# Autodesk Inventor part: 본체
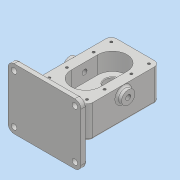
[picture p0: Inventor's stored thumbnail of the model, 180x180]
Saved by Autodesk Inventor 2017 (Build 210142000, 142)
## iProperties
Part Number: 본체
Material: 일반
Document SubType Name: Modeling
Designer: MRC
Density: 1 g/cm^3
Appearance: 기본값
Mass: 546.121 g
Surface Area: 823.386 cm^2
Volume: 546.121 cm^3
Author: MRC
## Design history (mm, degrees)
sketch "스케치1"
  geometry: L1 (40, -60)-(-40, -60); L2 (-40, -60)-(-40, 60); L3 (-40, 60)-(40, 60); L4 (40, 60)-(40, -60); L5 (40, -60)-(-40, 60); L6 (-40, -60)-(40, 60); 1 further point
  constraints: 12 end point, 2 midpoint, 2 parallel, 1 horizontal, 1 perpendicular
  dimensions: "d0" = 80 distance of L2.end L3.end; "d1" = 120 distance of L3.end L1.start
extrude "돌출1" new body sketch "스케치1" distance "d2" = 14; taper "d3" = 0 deg; dims "d5" = 39, "d6" = 0
fillet "모깎기1" dims "d4" = 9
sketch "스케치2"
  geometry: L1 (0, -49.175)-(0, 49.175); L2 (0, 22)-(0, -22); L3 (24, 22)-(24, -22); L4 (-24, -22)-(-24, 22); A1 r 24 centre (0, 22) between (24, 22) and (-24, 22); A2 r 24 centre (0, -22) between (-24, -22) and (24, -22); 2 further points
  constraints: 12 end point, 4 point on circle, 4 tangent, 2 centre point, 2 midpoint, 2 point on line, 1 coincident, 1 parallel, 1 vertical
  dimensions: "d12" = 22 distance of L2.start point (0, 0); "d13" = 24 radius of A1
extrude "돌출2" cut sketch "스케치2" distance "d14" = 29; taper "d15" = 0 deg
sketch "스케치3"
  geometry: C1 r 12.5 at (0, 22); C2 r 12.5 at (0, -22); A1 r 24 centre (0, 22) between (24, 22) and (-24, 22) reference; A2 r 24 centre (0, -22) between (-24, -22) and (24, -22) reference; 1 further point
  constraints: 2 centre point, 2 coincident
  dimensions: "d16" = 25 diameter of C1; "d17" = 25 diameter of C2
extrude "돌출3" cut sketch "스케치3" distance "d18" = 15; taper "d19" = 0 deg
chamfer "모따기1" distance "d20" = 1; stored, may be unused: second distance "d21" = 2, angle "d22" = 45 deg
sketch "스케치4"
  geometry: C1 r 19 at (0, 22); 1 further point
  constraints: 1 centre point, 1 vertical alignment
  dimensions: "d23" = 38 diameter of C1; "d24" = 22 distance of point (0, 0) C1.centre
extrude "돌출4" join sketch "스케치4" distance "d25" = 17; taper "d26" = 0 deg
sketch "스케치5"
  geometry: C1 r 19 at (0, 0) reference; C2 r 14 at (0, 0); 1 further point
  constraints: 1 centre point, 1 coincident
  dimensions: "d27" = 28 diameter of C2
extrude "돌출5" cut sketch "스케치5" distance "d28" = 7.3; taper "d29" = 0 deg
sketch "스케치6"
  geometry: C1 r 14 at (0, 0) reference; C2 r 8.5 at (0, 0); 1 further point
  constraints: 1 centre point, 1 coincident
  dimensions: "d30" = 17 diameter of C2
extrude "돌출6" cut sketch "스케치6" stored distance "d31" = 7.3; taper "d32" = 0 deg
fillet "모깎기2" dims "d33" = 0.5
sketch "스케치7"
  geometry: L1 (-80, 44)-(-90, 44); L2 (-90, 44)-(-90, -56); L3 (-90, -56)-(-80, -56); L4 (-80, -56)-(-80, 44); L5 (35.5, -15)-(46, -15) reference; L6 (46, -15)-(46, 14) reference; L7 (46, 14)-(60, 14) reference; L8 (60, 14)-(60, -39) reference; L9 (60, -39)-(41, -39) reference; L10 (41, -39)-(41, -56) reference; L11 (41, -56)-(36, -56) reference; L12 (36, -56)-(36, -49.2) reference; L13 (35.5, -48.7)-(30.5, -48.7) reference; L14 (30.5, -48.7)-(30.5, -30) reference; L15 (30.5, -30)-(34.5, -30) reference; L16 (34.5, -30)-(34.5, -16) reference; L17 (34.5, -16)-(35.5, -15) reference; L18 (-60, -39)-(-60, 14) reference; L19 (-60, 14)-(-46, 14) reference; L20 (-46, 14)-(-46, -15) reference; L21 (-46, -15)-(-35.5, -15) reference; L22 (-35.5, -15)-(-34.5, -16) reference; L23 (-34.5, -16)-(-34.5, -30) reference; L24 (-34.5, -30)-(-9.5, -30) reference; L25 (-9.5, -30)-(-9.5, -16) reference; L26 (-9.5, -16)-(-8.5, -15) reference; L27 (-8.5, -15)-(8.5, -15) reference; L28 (8.5, -15)-(9.5, -16) reference; L29 (9.5, -16)-(9.5, -30) reference; L30 (9.5, -30)-(13.5, -30) reference; L31 (13.5, -30)-(13.5, -48.7) reference; L32 (13.5, -48.7)-(8.5, -48.7) reference; L33 (8, -49.2)-(8, -56) reference; L34 (8, -56)-(3, -56) reference; L35 (3, -56)-(3, -39) reference; L36 (3, -39)-(-60, -39) reference; A1 r 0.5 centre (35.5, -49.2) between (36, -49.2) and (35.5, -48.7) reference; A2 r 0.5 centre (8.5, -49.2) between (8.5, -48.7) and (8, -49.2) reference; 1 further point
  constraints: 8 end point, 2 parallel, 1 collinear, 1 horizontal, 1 perpendicular
  dimensions: "d37" = 100 distance of L3.end L1.start; "d38" = 10 distance of L2.end L3.end; "d39" = 80 distance from line of L4 point (0, 0)
extrude "돌출7" join sketch "스케치7" stored distance "d40" = 120; taper "d41" = 0 deg
fillet "모깎기3" dims "d42" = 10
fillet "모깎기4" dims "d43" = 3
sketch "스케치8"
  geometry: L1 (-53, 0)-(-53, 102) reference; C1 r 11 at (-39, 51); 1 further point
  constraints: 1 centre point, 1 coincident
  dimensions: "d44" = 22 diameter of C1; "d45" = 14 distance from line of C1.centre L1
extrude "돌출8" join sketch "스케치8" distance "d46" = 8; taper "d47" = 0 deg
sketch "스케치10"
  geometry: C1 r 4.5 at (100, 7); C2 r 4.5 at (0, 7); C3 r 4.5 at (0, 87); C4 r 4.5 at (100, 87); A1 r 7 centre (0, 7) between (-7, 7) and (0, 0) reference; A2 r 7 centre (100, 7) between (100, 0) and (107, 7) reference; A3 r 7 centre (100, 87) between (107, 87) and (100, 94) reference; A4 r 7 centre (0, 87) between (0, 94) and (-7, 87) reference; 1 further point
  constraints: 4 centre point, 4 coincident
  dimensions: "d59" = 9 diameter of C1; "d60" = 9 diameter of C2; "d61" = 9 diameter of C3; "d62" = 9 diameter of C4
extrude "돌출9" cut sketch "스케치10" distance "d63" = 10; taper "d64" = 0 deg
sketch "스케치11"
  geometry: A1 r 9 centre (31, 51) between (40, 51) and (31, 60) reference; A2 r 9 centre (-31, 51) between (-31, 60) and (-40, 51) reference; 5 further points
  constraints: 4 vertical alignment
  dimensions: "d65" = 29 distance of point (-31, 22) A2.centre; "d66" = 44 distance of point (-31, -22) point (-31, 22); "d67" = 29 distance of point (31, 22) A1.centre; "d68" = 44 distance of point (31, -22) point (31, 22)
hole "구멍2" sketch "스케치11" at (-31, 22), (31, 22), (31, -22), (-31, -22) diameter "d69" = 4.134; stored, may be unused: countersink angle "d73" = 90 deg, drill point angle "d75" = 118 deg; dims "d70" = 10, "d71" = 4, "d72" = 2, "d74" = 12
hole "구멍3" diameter "d78" = 4.134; stored, may be unused: countersink angle "d82" = 90 deg, drill point angle "d84" = 118 deg; dims "d76" = 10, "d77" = 10, "d79" = 10, "d80" = 4, "d81" = 2, "d83" = 12
sketch "스케치15"
  geometry: L1 (-80, -39)-(-60, -27.453); L2 (-80, 14)-(-60, 2.453); L3 (-80, 34)-(-80, -46) reference; L4 (-60, -39)-(-60, 14) reference; L5 (-83, -56)-(-90, -56) reference; 1 further point
  constraints: 4 end point, 4 point on line
  dimensions: "d89" = 17 distance from line of L1.start L5; "d90" = 53 distance of L2.start L1.start; "d91" = 60 deg angle of L3 L1; "d92" = 60 deg angle of L3 L2
extrude "돌출10" join sketch "스케치15" stored distance "d93" = 48; taper "d94" = 0 deg
sketch "스케치16"
  geometry: L1 (-10, 87)-(-10, 7) reference; L2 (0, -3)-(100, -3) reference; 2 further points
  constraints: 1 other
  dimensions: "d95" = 60 distance from line of point (50, 7) L1; "d96" = 10 distance from line of L2 point (50, 7)
feature "엠보싱1" sketch "스케치16" dims "d0" = 80, "d1" = 120, "d13" = 24, "d97" = 0.5, "d98" = 0
fillet "모깎기5" dims "d99" = 3
fillet "모깎기6" dims "d100" = 3
fillet "모깎기7" dims "d101" = 3
chamfer "모따기3" distance "d102" = 0.7; stored, may be unused: second distance "d103" = 2, angle "d104" = 30 deg
hole "구멍4" diameter "d107" = 8.376; stored, may be unused: countersink angle "d111" = 90 deg, drill point angle "d113" = 118 deg; dims "d108" = 20, "d109" = 4, "d110" = 2, "d112" = 30, "d114" = 10, "d115" = 10
fillet "모깎기8" dims "d116" = 3
node "솔리드1"
mirror "미러1"
mirror "미러2"
mirror "미러3"
mirror "미러4"
node "절단 모서리 투영1"
